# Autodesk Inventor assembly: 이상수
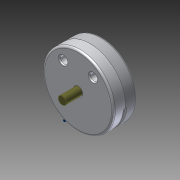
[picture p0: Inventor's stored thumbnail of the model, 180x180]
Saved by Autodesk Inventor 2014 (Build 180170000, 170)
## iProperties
Created: 2015-05
Part Number: 이상수
Document SubType Name: Assembly
Designer: USER
Author: USER
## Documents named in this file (10)
- C:\Users\basic\Desktop\Inventor2급-이상수\이상수.iam
- C:\Users\basic\Desktop\Inventor2급-이상수\이상수.ipt
- C:\Users\basic\Desktop\Inventor2급-이상수\20150513-2급공용부품\M 10 x 35.ipt
- C:\Users\basic\Desktop\Inventor2급-이상수\20150513-2급공용부품\덮개.ipt
- C:\Users\basic\Desktop\Inventor2급-이상수\20150513-2급공용부품\멈춤링.ipt
- C:\Users\basic\Desktop\Inventor2급-이상수\20150513-2급공용부품\베어링62_22.ipt
- C:\Users\basic\Desktop\Inventor2급-이상수\20150513-2급공용부품\슬라이더.ipt
- C:\Users\basic\Desktop\Inventor2급-이상수\20150513-2급공용부품\슬라이더2.ipt
- C:\Users\basic\Desktop\Inventor2급-이상수\20150513-2급공용부품\축.ipt
- C:\Users\basic\Desktop\Inventor2급-이상수\20150513-2급공용부품\평행핀.ipt
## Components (2 placed, 1 different names)
1. M 10 x 35:1
2. M 10 x 35:3
